(* Logix 5000 project; controller MNETR_V18 1756-L63 rev 18.11; software revision 18.01 *)

TASK MainTask (continuous, watchdog 500 ms) : MainProgram

MODULES
   Local : 1756-L63 (ICP 0, rev 18.11)
      LocalENBT : 1756-ENBT (Ethernet 105.102.0.224, ICP 3, rev 2.4)
         RemoteENBT : 1756-ENBT (Ethernet 105.102.0.210, rev 1.61, Output RPI 20 ms)
            MNETR : vendor 1 type 0 code 15 (ICP 1, rev 1.1, Output RPI 5 ms)
END_MODULES

TYPE MNETRBLOCKSTATS :   // This object is used to store the block transfer statistics for the MVI56-MNETR module.
STRUCT
   Read : INT;   // Total number of read block transfers
   Write : INT;   // Total number of write block transfers
   Parse : INT;   // Total number of blocks parsed
   Event : INT;   // Total number of event blocks received
   Cmd : INT;   // Total number of command blocks received
   Err : INT;   // Total number of block transfer errors
END_STRUCT
END_TYPE

TYPE MNETRCLIENTSTATS :   // This object is used to store client statistics for the MVI56-MNETR module.
STRUCT
   CmdReq : INT;   // Total number of command list requests sent
   CmdResp : INT;   // Total number of command list responses received
   CmdErr : INT;   // Total number of command list errors
   Requests : INT;   // Total number of requests for port
   Responses : INT;   // Total number of responses for port
   ErrSent : INT;   // Total number of errors sent
   ErrRec : INT;   // Total number of errors received
   CfgErrWord : INT;   // Configuration Error Word
   CurErr : INT;   // Current Error code
   LastErr : INT;   // Last recorded error code
END_STRUCT
END_TYPE

TYPE MNETRCLOCKTYPE :   // Allows read/write of clock value between the module and processor
STRUCT
   Read : BOOL;   // Reads current time from the module
   Write : BOOL;   // Writes current time from the module
   Config : MNETRDATETIME;   // Date and time configuration read or written between the module and processor
END_STRUCT
END_TYPE

TYPE MNETRCMDCONTROL :   // Controlling the Modbus Commands
STRUCT
   CmdIndex : INT[6];   // Stores the command indexes for command control.
   NumberOfCommands : INT;   // Number of commands per block (1 to 6)
   CommandsAddedtoQueue : INT;   // Number of commands added to queue
   CmdControlTrigger : BOOL;   // Trigger Command Control. User application will activate this trigger.
END_STRUCT
END_TYPE

TYPE MNETRCOILARRAY :   // Conversion to INT values
STRUCT
   Boolean : BOOL[416];   // Conversion from Bool to INT data types
END_STRUCT
END_TYPE

TYPE MNETRCONTROL :   // Module Behaviour Control Tags. Values used by program for data transfer operation between the module and the processor.
STRUCT
   BootTimer : TIMER;   // Starts counting when user issues a coldboot or warmboot
   WarmBoot : BOOL;   // Causes software reset. The Module reads new configuration information.
   ColdBoot : BOOL;   // Causes hardware reset.
   EventCmdTrigger : BOOL;   // Trigger events to be executed by the module
   EventCmd : MNETREVENTCMD;   // Event command Data
   CmdControl : MNETRCMDCONTROL;   // Command control data
   PassThru : MNETRPASSTHRU;   // Pass thru data format
   IPAddress : MNETRIPADDRESS;   // Getting and Setting IP address to and from Module
END_STRUCT
END_TYPE

TYPE MNETRDATA :   // Contains Read Data (data read from the module to the processor) and Write Data (data written from the processor to the module)
STRUCT
   ReadData : INT[600];   // Data read from module
   WriteData : INT[600];   // Data to write to module
END_STRUCT
END_TYPE

TYPE MNETRDATETIME :   // Stores the date and time value
STRUCT
   Year : DINT;
   Month : DINT;
   Day : DINT;
   Hour : DINT;
   Minute : DINT;
   Seconds : DINT;
END_STRUCT
END_TYPE

TYPE MNETRETHERNET :   // Stores the MVI56E-MNETR IP settings
STRUCT
   IP : INT[4];
   Netmask : INT[4];
   Gateway : INT[4];
END_STRUCT
END_TYPE

TYPE MNETRETHERNETTYPE :   // Allows read/write Ethernet settings between the module and processor
STRUCT
   Read : BOOL;   // Enable Ethernet configuration transfer from module to processor
   Write : BOOL;   // Enable Ethernet configuration transfer from processor to module
   Config : MNETRETHERNET;
END_STRUCT
END_TYPE

TYPE MNETREVENTCMD :   // Data structure to use for Event message generation.
STRUCT
   IP0 : INT;   // First digit of IP address
   IP1 : INT;   // Second digit of IP address
   IP2 : INT;   // Third digit of IP address
   IP3 : INT;   // Last digit of IP address
   ServPort : INT;   // TCP Service Port number (0-65535), 502 for MBAP, 2000 for MNET
   Node : INT;   // Modbus slave node address (0 to 247)
   DBAddress : INT;   // Module internal database to use with message
   Count : INT;   // Register or data point count
   Swap : INT;   // Swap code to use with functions 3 and 4
   Function : INT;   // Modbus function code for message
   Address : INT;   // Address to interface with in device
   Result : INT;   // shows the result of the event that was sent
END_STRUCT
END_TYPE

TYPE MNETRIPADDRESS :   // Data structure to get and set the IP address of the module.
STRUCT
   IPGetTrigger : BOOL;   // Gets IP address.
   IPReceived : INT[4];   // IP address received.
   IPSetTrigger : BOOL;   // Sets IP address
   IPRequested : INT[4];   // IP address set.
END_STRUCT
END_TYPE

TYPE MNETRMODULEDEF :   // this defines the whole module which includes all tags used in the program
STRUCT
   DATA : MNETRDATA;   // Data read from module
   STATUS : MNETRSTATUS;   // Client ,Server Status and blocks status
   CONTROL : MNETRCONTROL;   // Module control warmboot, coldboot, etc
   UTIL : MNETRUTIL;   // command, event control
END_STRUCT
END_TYPE

TYPE MNETRPASSTHRU :   // Applicable with the selection of a Pass-Through mode (1 to 3) in the Configuration file.
STRUCT
   MBControl1 : CONTROL;   // Modbus pass thru message control
   MBControl2 : CONTROL;   // Modbus pass thru message control
   MBMsg : SINT[500];   // message array
   MBScratch : INT[3];   // temporary used ints
   MBOffsetBit : INT;   // offset bit in the message
   MBOffset : INT;   // start offset in the message
   MBMsgLen : INT;   // message length
   mbdouble : DINT;   // Modbus double int tag
   MBCoil : MNETRCOILARRAY;   // Conversion array
END_STRUCT
END_TYPE

TYPE MNETRSTATUS :   // This status data is returned on each read block and can be used to detect proper module operation.
STRUCT
   PassCnt : INT;   // Program cycle counter
   ProductVersion : INT;   // Shows the module software version
   ProductCode : INT[2];   // This identifies the module product code
   BlockStats : MNETRBLOCKSTATS;   // Block Transfer Statistics.
   Reserved1 : INT;   // Reserved INT
   Reserved2 : INT;   // Reserved INT
   MNetReq : INT;   // number of remote client requests for port 502
   MNetResp : INT;   // number of server responses for port 502
   MBAPReq : INT;   // number of remote client requests for port 2000
   MBAPResp : INT;   // number of server responses for port 2000
   ClientStatus : MNETRCLIENTSTATS;   // Client Status
END_STRUCT
END_TYPE

TYPE MNETRUTIL :   // Variables for internal ladder usage - should not be accessed by user application
STRUCT
   LastRead : INT;   // Index of last read block
   LastWrite : INT;   // Index of last write block
   BlockIndex : INT;   // Computed block offset for data table
   ReadDataSizeGet : INT;   // Gets ReadData Array Length.
   WriteDataSizeGet : INT;   // Gets WriteData Array Length.
   ReadDataBlkCount : INT;   // Holds the value of the Block Counts of the Read Data Array. Array Size is divided by 40.
   WriteDataBlkCount : INT;   // Holds the value of the Block Counts of the Write Data Array. Array Size is divided by 40.
   RBTSremainder : INT;   // Holds remainder calculation value from the read array.
   WBTSremainder : INT;   // Holds remainder calculation value from the write array.
   IPsetPending : BOOL;   // Allows Setting module IP address
   IPgetPending : BOOL;   // Allows Getting module IP address
   InitOutBlkIDLim : INT;   // Block Index Limit for ReadData size of the array
END_STRUCT
END_TYPE

ADD_ON_INSTRUCTION AOI56EMNETR_OPTIONAL   (* revision 1.0 *)
// MVI56E-MNETR Optional Add-On Ethernet/Clock
// Revision note:
// Release
VAR_IN_OUT
   MVI56EMNETREthernet : MNETRETHERNETTYPE; {required}   // MVI56E-MCM Rev2 Ethernet Settings
   MVI56EMNETRClock : MNETRCLOCKTYPE; {required}   // MVI56E-MCM Rev2 Clock Settings
   ReadEthernetMSG : MESSAGE; {required}   // Read Ethernet Settings Message
   WriteEthernetMSG : MESSAGE; {required}   // Write Ethernet Settings Message
   ReadClockMSG : MESSAGE; {required}   // Read Clock Settings Message
   WriteClockMSG : MESSAGE; {required}   // Write Clock Settings Message
END_VAR

ROUTINE Logic   (* ladder *)
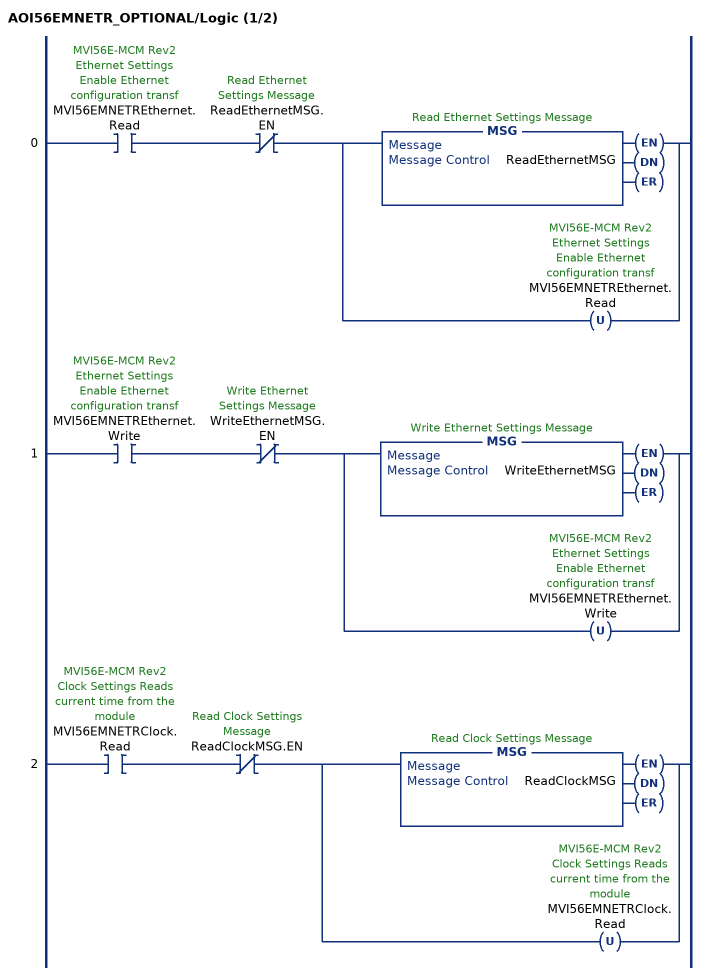
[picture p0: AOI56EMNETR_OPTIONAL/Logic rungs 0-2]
   0: XIC(MVI56EMNETREthernet.Read)XIO(ReadEthernetMSG.EN)[MSG(ReadEthernetMSG) ,OTU(MVI56EMNETREthernet.Read) ];
   1: XIC(MVI56EMNETREthernet.Write)XIO(WriteEthernetMSG.EN)[MSG(WriteEthernetMSG) ,OTU(MVI56EMNETREthernet.Write) ];
   2: XIC(MVI56EMNETRClock.Read)XIO(ReadClockMSG.EN)[MSG(ReadClockMSG) ,OTU(MVI56EMNETRClock.Read) ];
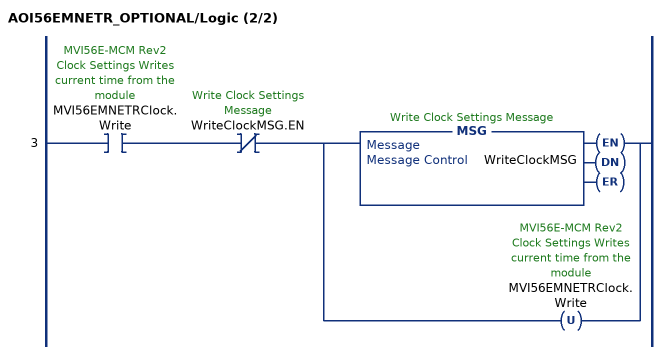
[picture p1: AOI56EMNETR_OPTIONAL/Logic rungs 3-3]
   3: XIC(MVI56EMNETRClock.Write)XIO(WriteClockMSG.EN)[MSG(WriteClockMSG) ,OTU(MVI56EMNETRClock.Write) ];
END_ROUTINE
END_ADD_ON_INSTRUCTION

ADD_ON_INSTRUCTION AOI56MNETR   (* revision 1.3, vendor ProSoft Technology Inc., ExecutePrescan *)
// Add-On - MVI56-MNETR & MVI56E-MNETR modules
// Revision note:
// v1.3 - 1) flexible read and write data arrays, 2) Includes blocks 9990/9991
VAR_IN_OUT
   Connection_Input : INT[42]; {required}   // Input parameters.
   Connection_Output : INT[42]; {required}   // Output parameters.
   MNETR : MNETRMODULEDEF; {required}
END_VAR
VAR
   MJFAULTS : DINT[12];
END_VAR

ROUTINE Logic   (* ladder *)
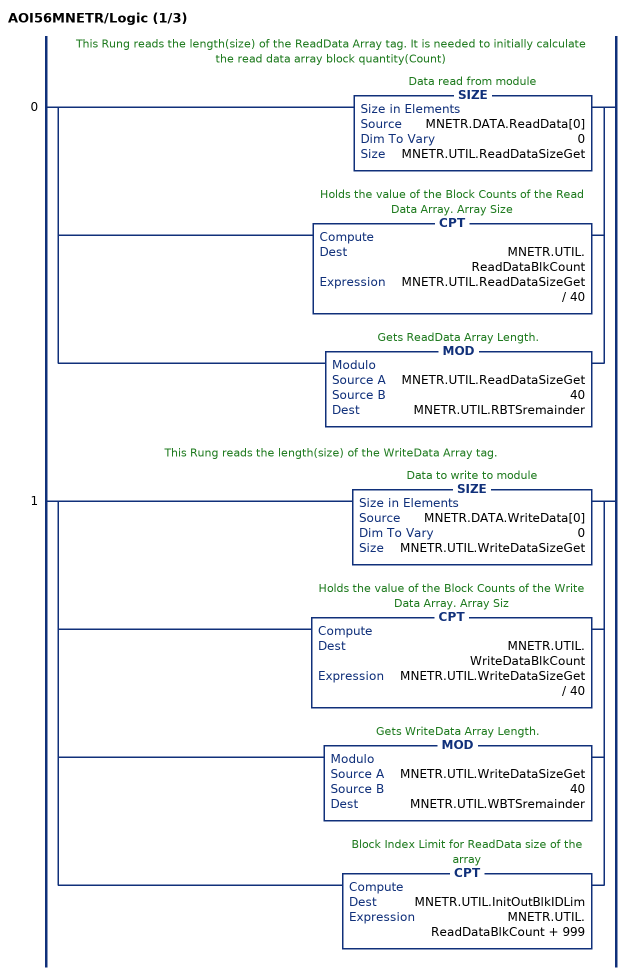
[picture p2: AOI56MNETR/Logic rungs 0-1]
   // This Rung reads the length(size) of the ReadData Array tag. It is needed to initially calculate the read data array block quantity(Count)
   0: [SIZE(MNETR.DATA.ReadData[0],0,MNETR.UTIL.ReadDataSizeGet) ,CPT(MNETR.UTIL.ReadDataBlkCount,MNETR.UTIL.ReadDataSizeGet / 40) ,MOD(MNETR.UTIL.ReadDataSizeGet,40,MNETR.UTIL.RBTSremainder) ];
   // This Rung reads the length(size) of the WriteData Array tag.
   1: [SIZE(MNETR.DATA.WriteData[0],0,MNETR.UTIL.WriteDataSizeGet) ,CPT(MNETR.UTIL.WriteDataBlkCount,MNETR.UTIL.WriteDataSizeGet / 40) ,MOD(MNETR.UTIL.WriteDataSizeGet,40,MNETR.UTIL.WBTSremainder) ,CPT(MNETR.UTIL.InitOutBlkIDLim,MNETR.UTIL.ReadDataBlkCount + 999) ];
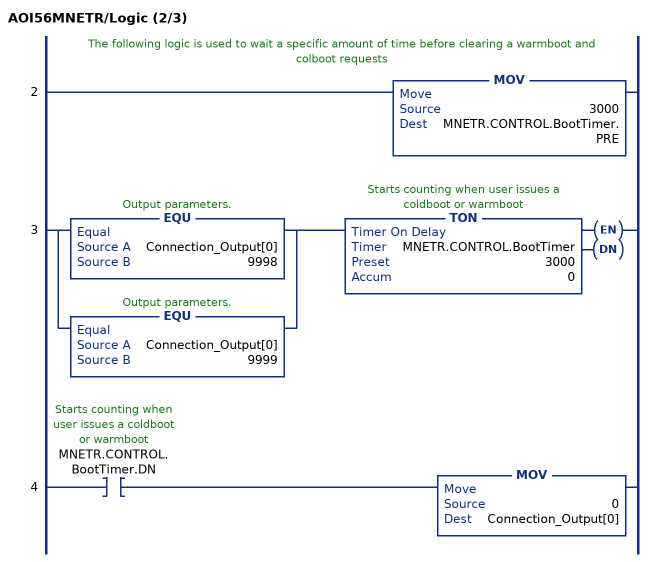
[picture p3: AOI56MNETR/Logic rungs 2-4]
   // The following logic is used to wait a specific amount of time before clearing a warmboot and colboot requests
   2: MOV(3000,MNETR.CONTROL.BootTimer.PRE);
   3: [EQU(Connection_Output[0],9998) ,EQU(Connection_Output[0],9999) ]TON(MNETR.CONTROL.BootTimer,3000,0);
   4: XIC(MNETR.CONTROL.BootTimer.DN)MOV(0,Connection_Output[0]);
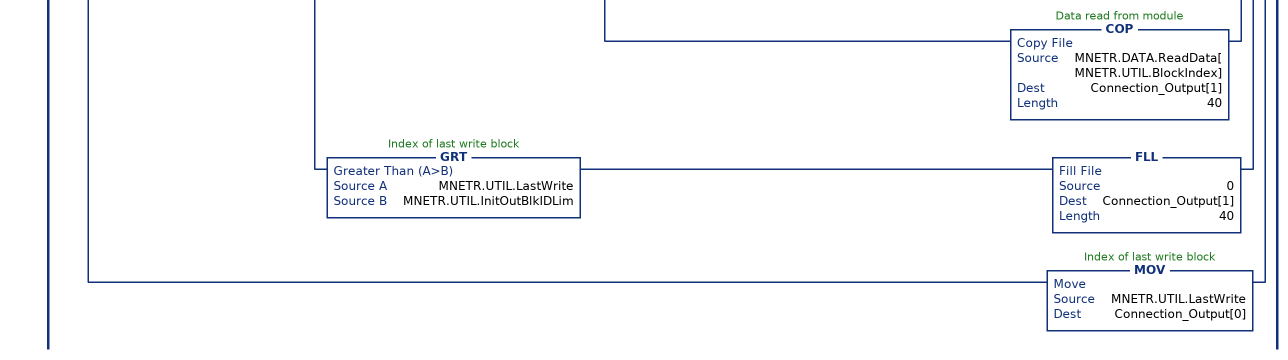
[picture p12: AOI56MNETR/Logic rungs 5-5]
   // This rung is used to check for a new read block from the MVI56-MNETR.  If new data is available, the LastRead and Input Image Word[41] will not be equal.  This will force the program to call the ReadData subroutine to process the new data received.  After the new data is placed in the ReadData controller tags, the program will send new data to the module using the WriteData subroutine.
   5: NEQ(Connection_Input[41],MNETR.UTIL.LastRead)[MOV(Connection_Input[41],MNETR.UTIL.LastRead) ,[EQU(-1,MNETR.UTIL.LastRead) ,EQU(0,MNETR.UTIL.LastRead) ] [COP(Connection_Input[1],MNETR.STATUS.PassCnt,1) ,COP(Connection_Input[2],MNETR.STATUS.BlockStats.Read,6) ,COP(Connection_Input[8],MNETR.STATUS.Reserved1,6) ,COP(Connection_Input[14],MNETR.STATUS.ClientStatus.CmdReq,10) ,COP(Connection_Input[24],MNETR.STATUS.ProductCode[0],2) ,COP(Connection_Input[26],MNETR.STATUS.ProductVersion,1) ] ,GEQ(MNETR.UTIL.LastRead,1) [LEQ(MNETR.UTIL.LastRead,MNETR.UTIL.ReadDataBlkCount) [CPT(MNETR.UTIL.BlockIndex,(MNETR.UTIL.LastRead - 1) * 40) ,COP(Connection_Input[1],MNETR.DATA.ReadData[MNETR.UTIL.BlockIndex],40) ] ,CMP(MNETR.UTIL.LastRead - MNETR.UTIL.ReadDataBlkCount = 1) GRT(MNETR.UTIL.RBTSremainder,0) [CPT(MNETR.UTIL.BlockIndex,(MNETR.UTIL.LastRead-1) * 40) ,COP(Connection_Input[1],MNETR.DATA.ReadData[MNETR.UTIL.BlockIndex],MNETR.UTIL.RBTSremainder) ] ] ,EQU(MNETR.UTIL.LastRead,9990) [COP(Connection_Input[1],MNETR.CONTROL.IPAddress.IPRequested[0],4) ,OTU(MNETR.UTIL.IPsetPending) ] ,EQU(MNETR.UTIL.LastRead,9991) [COP(Connection_Input[1],MNETR.CONTROL.IPAddress.IPReceived[0],4) ,OTU(MNETR.UTIL.IPgetPending) ] ,EQU(MNETR.UTIL.LastRead,2000) MOV(Connection_Input[1],MNETR.CONTROL.EventCmd.Result) ,LIM(5001,MNETR.UTIL.LastRead,5006) MOV(Connection_Input[1],MNETR.CONTROL.CmdControl.CommandsAddedtoQueue) ,EQU(9996,MNETR.UTIL.LastRead) [MOV(Connection_Input[1],MNETR.CONTROL.PassThru.MBMsgLen) ,COP(Connection_Input[3],MNETR.CONTROL.PassThru.MBMsg[0],MNETR.CONTROL.PassThru.MBMsgLen) ] ,LIM(9956,MNETR.UTIL.LastRead,9957) [MOV(Connection_Input[2],MNETR.CONTROL.PassThru.MBOffset) ,LES(MNETR.CONTROL.PassThru.MBOffset,MNETR.UTIL.WriteDataSizeGet) COP(Connection_Input[3],MNETR.DATA.WriteData[MNETR.CONTROL.PassThru.MBOffset],Connection_Input[1]) ] ,EQU(9958,MNETR.UTIL.LastRead) [MOV(Connection_Input[2],MNETR.CONTROL.PassThru.MBOffsetBit) ,MOV(Connection_Input[3],MNETR.CONTROL.PassThru.MBScratch[2]) ,DIV(MNETR.CONTROL.PassThru.MBOffsetBit,16,MNETR.CONTROL.PassThru.MBOffset) ,MOD(MNETR.CONTROL.PassThru.MBOffsetBit,16,MNETR.CONTROL.PassThru.MBOffsetBit) ,XPY(2,MNETR.CONTROL.PassThru.MBOffsetBit,MNETR.CONTROL.PassThru.mbdouble) ,MVM(MNETR.CONTROL.PassThru.mbdouble,16#0000_ffff,MNETR.CONTROL.PassThru.MBOffsetBit) ,NEQ(MNETR.CONTROL.PassThru.MBScratch[2],0) OR(MNETR.CONTROL.PassThru.MBOffsetBit,MNETR.DATA.WriteData[MNETR.CONTROL.PassThru.MBOffset],MNETR.DATA.WriteData[MNETR.CONTROL.PassThru.MBOffset]) ,EQU(MNETR.CONTROL.PassThru.MBScratch[2],0) [NOT(MNETR.CONTROL.PassThru.MBOffsetBit,MNETR.CONTROL.PassThru.MBOffsetBit) ,AND(MNETR.CONTROL.PassThru.MBOffsetBit,MNETR.DATA.WriteData[MNETR.CONTROL.PassThru.MBOffset],MNETR.DATA.WriteData[MNETR.CONTROL.PassThru.MBOffset]) ] ] ,EQU(9959,MNETR.UTIL.LastRead) [MOV(Connection_Input[2],MNETR.CONTROL.PassThru.MBOffset) ,MOV(Connection_Input[1],MNETR.CONTROL.PassThru.MBControl1.LEN) ,MOV(Connection_Input[1],MNETR.CONTROL.PassThru.MBControl2.LEN) ,FAL(MNETR.CONTROL.PassThru.MBControl1,2,0,ALL,MNETR.DATA.WriteData[MNETR.CONTROL.PassThru.MBOffset+MNETR.CONTROL.PassThru.MBControl1.POS],MNETR.DATA.WriteData[MNETR.CONTROL.PassThru.MBOffset+MNETR.CONTROL.PassThru.MBControl1.POS] AND(NOT Connection_Input[14+MNETR.CONTROL.PassThru.MBControl1.POS])) ,FAL(MNETR.CONTROL.PassThru.MBControl2,2,0,ALL,MNETR.DATA.WriteData[MNETR.CONTROL.PassThru.MBOffset+MNETR.CONTROL.PassThru.MBControl2.POS],MNETR.DATA.WriteData[MNETR.CONTROL.PassThru.MBOffset+MNETR.CONTROL.PassThru.MBControl2.POS] OR(Connection_Input[14+MNETR.CONTROL.PassThru.MBControl2.POS] AND Connection_Input[3+MNETR.CONTROL.PassThru.MBControl2.POS])) ] ,EQU(9961,MNETR.UTIL.LastRead) [MOV(Connection_Input[1],MNETR.CONTROL.PassThru.MBMsgLen) ,CPT(MNETR.CONTROL.PassThru.MBMsgLen,MNETR.CONTROL.PassThru.MBMsgLen*2+2) ,COP(Connection_Input[3],MNETR.CONTROL.PassThru.MBMsg[0],MNETR.CONTROL.PassThru.MBMsgLen) ] ,MOV(Connection_Input[0],MNETR.UTIL.LastWrite) ,XIC(MNETR.CONTROL.WarmBoot) [MOV(9998,MNETR.UTIL.LastWrite) ,OTU(MNETR.CONTROL.WarmBoot) ] ,XIC(MNETR.CONTROL.ColdBoot) [MOV(9999,MNETR.UTIL.LastWrite) ,OTU(MNETR.CONTROL.ColdBoot) ] ,XIC(MNETR.CONTROL.IPAddress.IPSetTrigger) XIO(MNETR.UTIL.IPsetPending) [COP(MNETR.CONTROL.IPAddress.IPRequested[0],Connection_Output[1],4) ,MOV(9990,MNETR.UTIL.LastWrite) ,OTU(MNETR.CONTROL.IPAddress.IPSetTrigger) ,OTL(MNETR.UTIL.IPsetPending) ] ,XIC(MNETR.CONTROL.IPAddress.IPGetTrigger) XIO(MNETR.UTIL.IPgetPending) [MOV(9991,MNETR.UTIL.LastWrite) ,OTU(MNETR.CONTROL.IPAddress.IPGetTrigger) ,OTL(MNETR.UTIL.IPgetPending) ] ,XIC(MNETR.CONTROL.CmdControl.CmdControlTrigger) [CPT(MNETR.UTIL.LastWrite,5000+MNETR.CONTROL.CmdControl.NumberOfCommands) ,COP(MNETR.CONTROL.CmdControl.CmdIndex[0],Connection_Output[1],6) ,CPT(Connection_Output[0],5000+MNETR.CONTROL.CmdControl.NumberOfCommands) ,OTU(MNETR.CONTROL.CmdControl.CmdControlTrigger) ] ,XIC(MNETR.CONTROL.EventCmdTrigger) [MOV(2000,MNETR.UTIL.LastWrite) ,COP(MNETR.CONTROL.EventCmd.IP0,Connection_Output[1],11) ,OTU(MNETR.CONTROL.EventCmdTrigger) ] ,GEQ(MNETR.UTIL.LastWrite,1) [LEQ(MNETR.UTIL.LastWrite,MNETR.UTIL.WriteDataBlkCount) [CPT(MNETR.UTIL.BlockIndex,(MNETR.UTIL.LastWrite - 1) * 40) ,COP(MNETR.DATA.WriteData[MNETR.UTIL.BlockIndex],Connection_Output[1],40) ] ,CMP(MNETR.UTIL.LastWrite - MNETR.UTIL.WriteDataBlkCount = 1) GRT(MNETR.UTIL.WBTSremainder,0) [CPT(MNETR.UTIL.BlockIndex,(MNETR.UTIL.LastWrite-1) * 40) ,COP(MNETR.DATA.WriteData[MNETR.UTIL.BlockIndex],Connection_Output[1],MNETR.UTIL.WBTSremainder) ] ] ,LIM(1000,MNETR.UTIL.LastWrite,1124) [LEQ(MNETR.UTIL.LastWrite,MNETR.UTIL.InitOutBlkIDLim) [CPT(MNETR.UTIL.BlockIndex,(MNETR.UTIL.LastWrite - 1000) * 40) ,COP(MNETR.DATA.ReadData[MNETR.UTIL.BlockIndex],Connection_Output[1],40) ] ,GRT(MNETR.UTIL.LastWrite,MNETR.UTIL.InitOutBlkIDLim) FLL(0,Connection_Output[1],40) ] ,MOV(MNETR.UTIL.LastWrite,Connection_Output[0]) ];
END_ROUTINE

ROUTINE Prescan   (* ladder *)
// Prescan
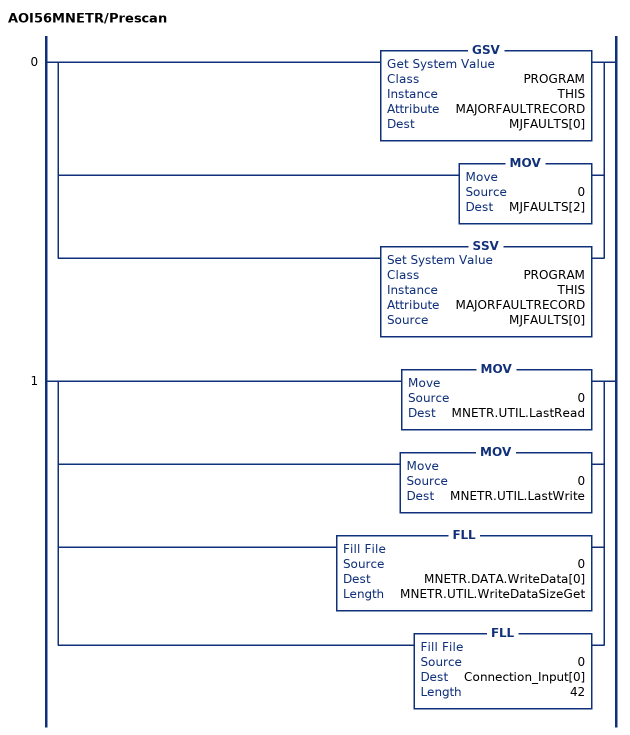
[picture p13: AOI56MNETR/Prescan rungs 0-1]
   0: [GSV(PROGRAM,THIS,MAJORFAULTRECORD,MJFAULTS[0]) ,MOV(0,MJFAULTS[2]) ,SSV(PROGRAM,THIS,MAJORFAULTRECORD,MJFAULTS[0]) ];
   1: [MOV(0,MNETR.UTIL.LastRead) ,MOV(0,MNETR.UTIL.LastWrite) ,FLL(0,MNETR.DATA.WriteData[0],MNETR.UTIL.WriteDataSizeGet) ,FLL(0,Connection_Input[0],42) ];
END_ROUTINE
END_ADD_ON_INSTRUCTION

VAR_GLOBAL   (* controller tags *)
   AOI56EMNETR_Optional : AOI56EMNETR_OPTIONAL;
   AOI56MNETR : AOI56MNETR;
   MNETR : MNETRMODULEDEF;
   MVI56EMNETRClock : MNETRCLOCKTYPE;
   MVI56EMNETREthernet : MNETRETHERNETTYPE;
   ReadClockMSG : MESSAGE;
        MessageParameters(ServiceCode := 16#000e, DestinationTag := MVI56EMNETRClock.Config, ...)
   ReadEthernetMSG : MESSAGE;
        MessageParameters(ServiceCode := 16#000e, DestinationTag := MVI56EMNETREthernet.Config, ...)
   WriteClockMSG : MESSAGE;
        MessageParameters(ServiceCode := 16#0010, LocalElement := MVI56EMNETRClock.Config, ...)
   WriteEthernetMSG : MESSAGE;
        MessageParameters(ServiceCode := 16#0010, LocalElement := MVI56EMNETREthernet.Config, ...)
END_VAR

PROGRAM MainProgram   (* main routine MainRoutine *)

ROUTINE MainRoutine   (* ladder *)
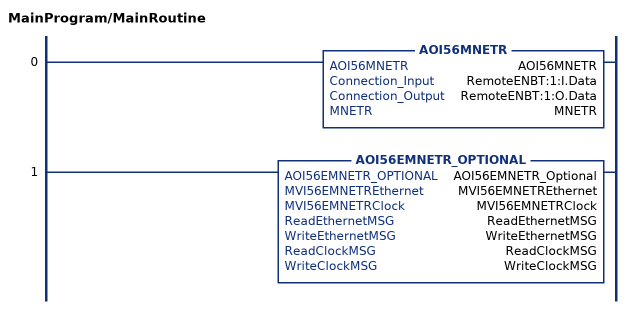
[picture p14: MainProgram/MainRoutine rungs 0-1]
   0: AOI56MNETR(AOI56MNETR,RemoteENBT:1:I.Data,RemoteENBT:1:O.Data,MNETR);
   1: AOI56EMNETR_OPTIONAL(AOI56EMNETR_Optional,MVI56EMNETREthernet,MVI56EMNETRClock,ReadEthernetMSG,WriteEthernetMSG,ReadClockMSG,WriteClockMSG);
END_ROUTINE
END_PROGRAM
